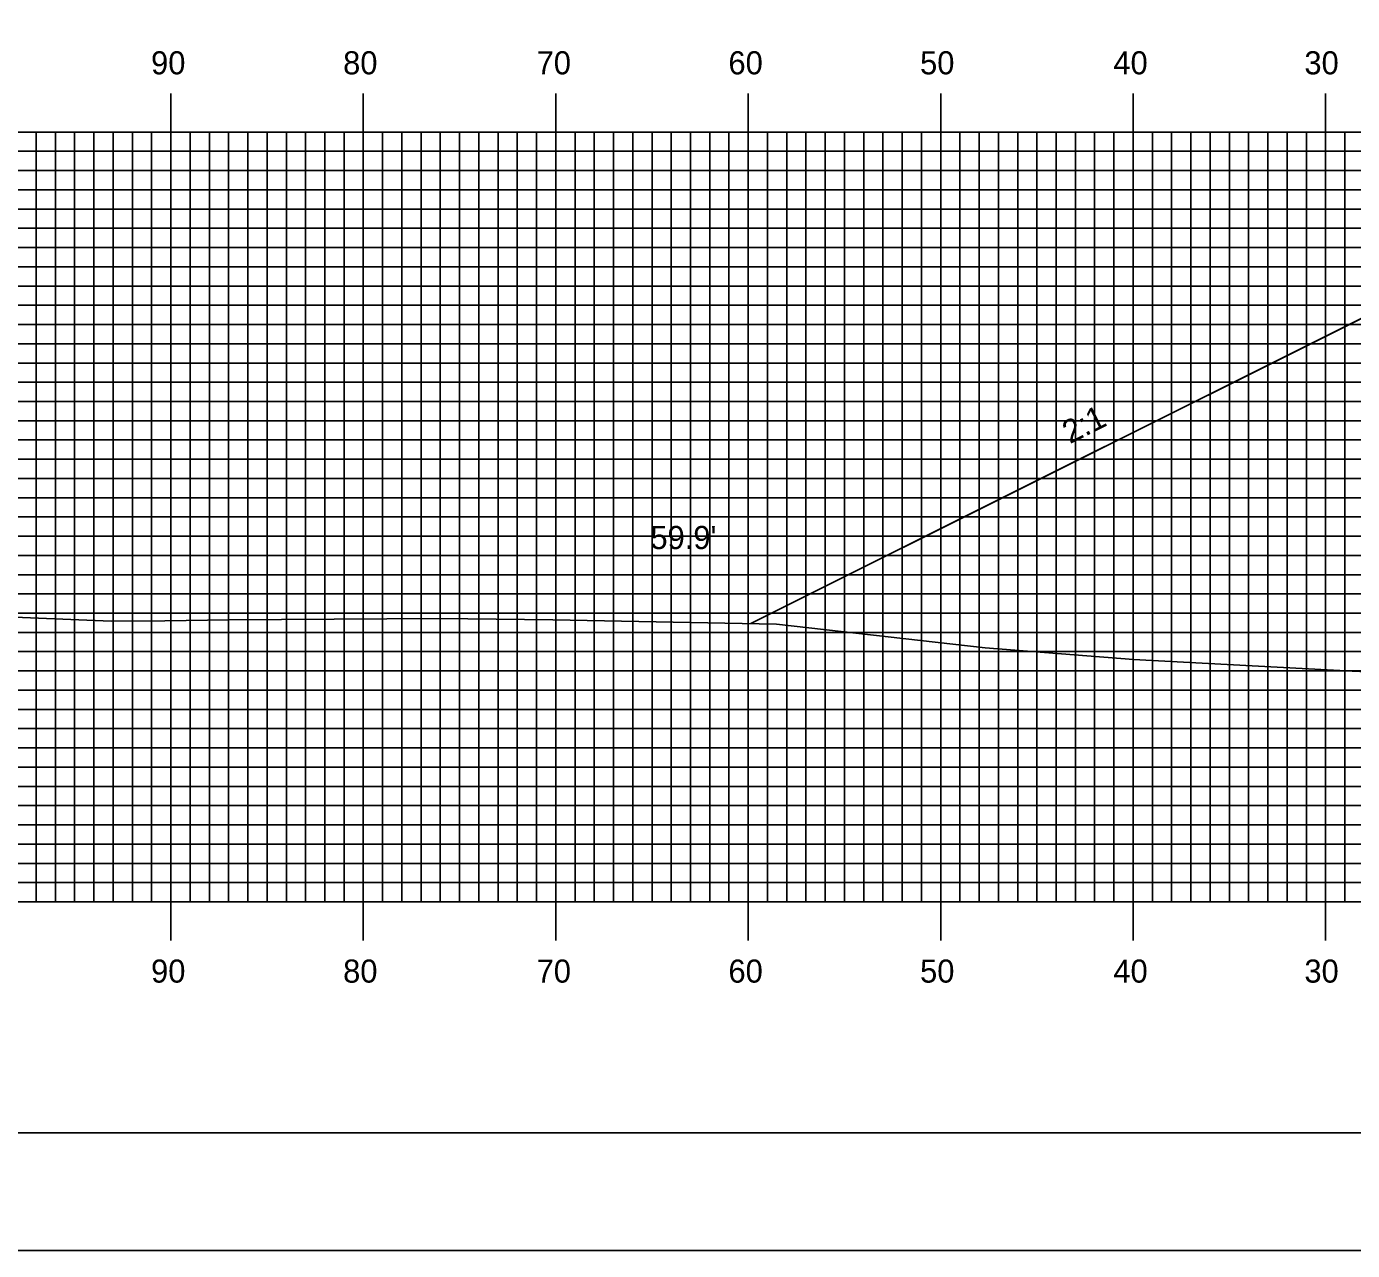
# Model space of a CAD drawing. Extents: x 1812948 to 1813291, y 442591 to 442811.
# Drawn here: x 1813016 to 1813084.9, y 442590.5 to 442654.2 of the extents above; entities that cross this region are included whole.
import ezdxf

# ---------------------------------------------------------------- set-up
doc = ezdxf.new("R2010")
doc.units = 0
for name, color, linetype in [('ANNOTATION', 7, 'Continuous'), ('BORDER', 7, 'Continuous'), ('D_Roadway_Centerline', 7, 'Continuous'), ('D_Roadway_SlopeLines', 7, 'Continuous'), ('D_Text_Standard', 7, 'Continuous'), ('H_V ANNOTATION', 7, 'Continuous'), ('MAJOR', 7, 'Continuous'), ('MINOR', 7, 'Continuous'), ('PLOT BOUNDARY', 7, 'Continuous'), ('S_Roadway_Centerline', 7, 'Continuous')]:
    doc.layers.add(name, color=color, linetype=linetype)

msp = doc.modelspace()

# ---------------------------------------------------------------- linework, layer by layer
at = {"layer": 'BORDER'}
msp.add_lwpolyline([(1812963.855, 442596.665), (1813283.855, 442596.665), (1813283.855, 442806.665), (1812963.855, 442806.665)], close=True, dxfattribs=at)
at = {"layer": 'D_Roadway_Centerline'}
msp.add_lwpolyline([(1813053.588, 442623.121), (1813085.247, 442638.95), (1813090.455, 442641.555), (1813093.455, 442641.615), (1813101.455, 442641.775), (1813113.455, 442641.199), (1813125.455, 442640.623), (1813133.455, 442640.239), (1813136.455, 442640.095), (1813141.986, 442637.329), (1813180.406, 442618.119)], dxfattribs=at)
at = {"layer": 'D_Roadway_SlopeLines'}
msp.add_lwpolyline([(1813090.455, 442641.555), (1813053.588, 442623.121)], dxfattribs=at)
at = {"layer": 'MAJOR'}
for p, q in [((1813023.455, 442650.669), (1813023.455, 442648.665)), ((1813033.455, 442650.669), (1813033.455, 442648.665)), ((1813043.455, 442650.669), (1813043.455, 442648.665)), ((1813053.455, 442650.669), (1813053.455, 442648.665)), ((1813063.455, 442650.669), (1813063.455, 442648.665)), ((1813073.455, 442650.669), (1813073.455, 442648.665)), ((1813083.455, 442650.669), (1813083.455, 442648.665)), ((1812973.455, 442648.665), (1813253.455, 442648.665)), ((1812973.455, 442648.665), (1813253.455, 442648.665)), ((1813023.455, 442608.665), (1813023.455, 442648.665)), ((1813033.455, 442608.665), (1813033.455, 442648.665)), ((1813043.455, 442608.665), (1813043.455, 442648.665)), ((1813053.455, 442608.665), (1813053.455, 442648.665)), ((1813063.455, 442608.665), (1813063.455, 442648.665)), ((1813073.455, 442608.665), (1813073.455, 442648.665)), ((1813083.455, 442608.665), (1813083.455, 442648.665)), ((1812973.455, 442643.665), (1813253.455, 442643.665)), ((1812973.455, 442638.665), (1813253.455, 442638.665)), ((1812973.455, 442633.665), (1813253.455, 442633.665)), ((1812973.455, 442628.665), (1813253.455, 442628.665)), ((1812973.455, 442623.665), (1813253.455, 442623.665)), ((1812973.455, 442618.665), (1813253.455, 442618.665)), ((1812973.455, 442613.665), (1813253.455, 442613.665)), ((1812973.455, 442608.665), (1813253.455, 442608.665)), ((1812973.455, 442608.665), (1813253.455, 442608.665)), ((1813023.455, 442606.661), (1813023.455, 442608.665)), ((1813033.455, 442606.661), (1813033.455, 442608.665)), ((1813043.455, 442606.661), (1813043.455, 442608.665)), ((1813053.455, 442606.661), (1813053.455, 442608.665)), ((1813063.455, 442606.661), (1813063.455, 442608.665)), ((1813073.455, 442606.661), (1813073.455, 442608.665)), ((1813083.455, 442606.661), (1813083.455, 442608.665))]:
    msp.add_line(p, q, dxfattribs=at)
at = {"layer": 'MINOR'}
for p, q in [((1813016.455, 442608.665), (1813016.455, 442648.665)), ((1813017.455, 442608.665), (1813017.455, 442648.665)), ((1813018.455, 442608.665), (1813018.455, 442648.665)), ((1813019.455, 442608.665), (1813019.455, 442648.665)), ((1813020.455, 442608.665), (1813020.455, 442648.665)), ((1813021.455, 442608.665), (1813021.455, 442648.665)), ((1813022.455, 442608.665), (1813022.455, 442648.665)), ((1813024.455, 442608.665), (1813024.455, 442648.665)), ((1813025.455, 442608.665), (1813025.455, 442648.665)), ((1813026.455, 442608.665), (1813026.455, 442648.665)), ((1813027.455, 442608.665), (1813027.455, 442648.665)), ((1813028.455, 442608.665), (1813028.455, 442648.665)), ((1813029.455, 442608.665), (1813029.455, 442648.665)), ((1813030.455, 442608.665), (1813030.455, 442648.665)), ((1813031.455, 442608.665), (1813031.455, 442648.665)), ((1813032.455, 442608.665), (1813032.455, 442648.665)), ((1813034.455, 442608.665), (1813034.455, 442648.665)), ((1813035.455, 442608.665), (1813035.455, 442648.665)), ((1813036.455, 442608.665), (1813036.455, 442648.665)), ((1813037.455, 442608.665), (1813037.455, 442648.665)), ((1813038.455, 442608.665), (1813038.455, 442648.665)), ((1813039.455, 442608.665), (1813039.455, 442648.665)), ((1813040.455, 442608.665), (1813040.455, 442648.665)), ((1813041.455, 442608.665), (1813041.455, 442648.665)), ((1813042.455, 442608.665), (1813042.455, 442648.665)), ((1813044.455, 442608.665), (1813044.455, 442648.665)), ((1813045.455, 442608.665), (1813045.455, 442648.665)), ((1813046.455, 442608.665), (1813046.455, 442648.665)), ((1813047.455, 442608.665), (1813047.455, 442648.665)), ((1813048.455, 442608.665), (1813048.455, 442648.665)), ((1813049.455, 442608.665), (1813049.455, 442648.665)), ((1813050.455, 442608.665), (1813050.455, 442648.665)), ((1813051.455, 442608.665), (1813051.455, 442648.665)), ((1813052.455, 442608.665), (1813052.455, 442648.665)), ((1813054.455, 442608.665), (1813054.455, 442648.665)), ((1813055.455, 442608.665), (1813055.455, 442648.665)), ((1813056.455, 442608.665), (1813056.455, 442648.665)), ((1813057.455, 442608.665), (1813057.455, 442648.665)), ((1813058.455, 442608.665), (1813058.455, 442648.665)), ((1813059.455, 442608.665), (1813059.455, 442648.665)), ((1813060.455, 442608.665), (1813060.455, 442648.665)), ((1813061.455, 442608.665), (1813061.455, 442648.665)), ((1813062.455, 442608.665), (1813062.455, 442648.665)), ((1813064.455, 442608.665), (1813064.455, 442648.665)), ((1813065.455, 442608.665), (1813065.455, 442648.665)), ((1813066.455, 442608.665), (1813066.455, 442648.665)), ((1813067.455, 442608.665), (1813067.455, 442648.665)), ((1813068.455, 442608.665), (1813068.455, 442648.665)), ((1813069.455, 442608.665), (1813069.455, 442648.665)), ((1813070.455, 442608.665), (1813070.455, 442648.665)), ((1813071.455, 442608.665), (1813071.455, 442648.665)), ((1813072.455, 442608.665), (1813072.455, 442648.665)), ((1813074.455, 442608.665), (1813074.455, 442648.665)), ((1813075.455, 442608.665), (1813075.455, 442648.665)), ((1813076.455, 442608.665), (1813076.455, 442648.665)), ((1813077.455, 442608.665), (1813077.455, 442648.665)), ((1813078.455, 442608.665), (1813078.455, 442648.665)), ((1813079.455, 442608.665), (1813079.455, 442648.665)), ((1813080.455, 442608.665), (1813080.455, 442648.665)), ((1813081.455, 442608.665), (1813081.455, 442648.665)), ((1813082.455, 442608.665), (1813082.455, 442648.665)), ((1813084.455, 442608.665), (1813084.455, 442648.665)), ((1812973.455, 442647.665), (1813253.455, 442647.665)), ((1812973.455, 442646.665), (1813253.455, 442646.665)), ((1812973.455, 442645.665), (1813253.455, 442645.665)), ((1812973.455, 442644.665), (1813253.455, 442644.665)), ((1812973.455, 442642.665), (1813253.455, 442642.665)), ((1812973.455, 442641.665), (1813253.455, 442641.665)), ((1812973.455, 442640.665), (1813253.455, 442640.665)), ((1812973.455, 442639.665), (1813253.455, 442639.665)), ((1812973.455, 442637.665), (1813253.455, 442637.665)), ((1812973.455, 442636.665), (1813253.455, 442636.665)), ((1812973.455, 442635.665), (1813253.455, 442635.665)), ((1812973.455, 442634.665), (1813253.455, 442634.665)), ((1812973.455, 442632.665), (1813253.455, 442632.665)), ((1812973.455, 442631.665), (1813253.455, 442631.665)), ((1812973.455, 442630.665), (1813253.455, 442630.665)), ((1812973.455, 442629.665), (1813253.455, 442629.665)), ((1812973.455, 442627.665), (1813253.455, 442627.665)), ((1812973.455, 442626.665), (1813253.455, 442626.665)), ((1812973.455, 442625.665), (1813253.455, 442625.665)), ((1812973.455, 442624.665), (1813253.455, 442624.665)), ((1812973.455, 442622.665), (1813253.455, 442622.665)), ((1812973.455, 442621.665), (1813253.455, 442621.665)), ((1812973.455, 442620.665), (1813253.455, 442620.665)), ((1812973.455, 442619.665), (1813253.455, 442619.665)), ((1812973.455, 442617.665), (1813253.455, 442617.665)), ((1812973.455, 442616.665), (1813253.455, 442616.665)), ((1812973.455, 442615.665), (1813253.455, 442615.665)), ((1812973.455, 442614.665), (1813253.455, 442614.665)), ((1812973.455, 442612.665), (1813253.455, 442612.665)), ((1812973.455, 442611.665), (1813253.455, 442611.665)), ((1812973.455, 442610.665), (1813253.455, 442610.665)), ((1812973.455, 442609.665), (1813253.455, 442609.665))]:
    msp.add_line(p, q, dxfattribs=at)
at = {"layer": 'PLOT BOUNDARY'}
msp.add_lwpolyline([(1812947.668, 442590.547), (1813287.668, 442590.547), (1813287.668, 442810.547), (1812947.668, 442810.547)], close=True, dxfattribs=at)
at = {"layer": 'S_Roadway_Centerline'}
msp.add_lwpolyline([(1812973.455, 442623.156), (1812980.902, 442623.082), (1812986.103, 442623.273), (1812995.124, 442623.509), (1813003.928, 442623.532), (1813007.767, 442623.769), (1813020.357, 442623.244), (1813023.134, 442623.274), (1813026.473, 442623.326), (1813037.416, 442623.381), (1813043.299, 442623.318), (1813054.922, 442623.096), (1813065.769, 442621.862), (1813073.47, 442621.262), (1813084.84, 442620.644), (1813088.359, 442620.497)], dxfattribs=at)

# ---------------------------------------------------------------- texts
at = {"layer": 'ANNOTATION'}
msp.add_text('2:1', height=1.2, rotation=26.56505, dxfattribs=at).set_placement((1813070.167, 442632.447))
at = {"layer": 'D_Text_Standard'}
msp.add_text("59.9'", height=1.2, dxfattribs=at).set_placement((1813048.372, 442626.997))
at = {"layer": 'H_V ANNOTATION'}
for s, p in [('90', (1813022.427, 442651.665)), ('80', (1813032.406, 442651.665)), ('70', (1813042.459, 442651.665)), ('60', (1813052.427, 442651.665)), ('50', (1813062.384, 442651.665)), ('40', (1813072.427, 442651.665)), ('30', (1813082.352, 442651.665)), ('90', (1813022.427, 442604.465)), ('80', (1813032.406, 442604.465)), ('70', (1813042.459, 442604.465)), ('60', (1813052.427, 442604.465)), ('50', (1813062.384, 442604.465)), ('40', (1813072.427, 442604.465)), ('30', (1813082.352, 442604.465))]:
    msp.add_text(s, height=1.2, dxfattribs=at).set_placement(p)

doc.saveas('drawing.dxf')
